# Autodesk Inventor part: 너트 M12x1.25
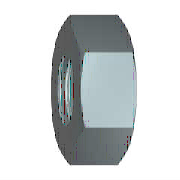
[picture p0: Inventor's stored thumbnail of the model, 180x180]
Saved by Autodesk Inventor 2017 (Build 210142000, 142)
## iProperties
IsCustomPart: 1
Created: 2012-02
Part Number: 너트 M12x1.25
Material: 강철, 연강
Description: 6각 너트
Document SubType Name: Modeling
Standard: KS B 1012
Designer: mduedu
Standards Organization: KS
Language: ko-KR
Size Designation: M12x1.25
Categories: <MemberInstance><Categories><Category DisplayName="조임쇠" InternalName="e4da775c-781d-43d5-af7c-5136215cf5a6" Mnemonic="FSTN"><Category DisplayName="너트" InternalN
Density: 1 g/cm^3
Appearance: Steel
Author: mduedu
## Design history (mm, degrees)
sketch "스케치1"
  geometry: L1 (-10.97, 0)-(-5.485, 9.5); L2 (-5.485, 9.5)-(5.485, 9.5); L3 (5.485, 9.5)-(10.97, 0); L4 (10.97, 0)-(5.485, -9.5); L5 (5.485, -9.5)-(-5.485, -9.5); L6 (-5.485, -9.5)-(-10.97, 0); 2 further points
  constraints: 12 end point, 1 coincident, 1 horizontal, 11 other
  dimensions: "d0" = 21.93931 distance of L3.end L1.start (= 1.1547 x SW)
extrude "본체" new body sketch "스케치1" distance "d1" = 10 (= KOH); taper "d2" = 0 deg
sketch "스케치2"
  geometry: L1 (0, 5.485)-(0, 10.97) reference; L2 (0, 10.97)-(10, 10.97) reference; L3 (10, 5.485)-(10, 10.97) reference; L4 (-2, 0)-(12, 0) reference; L5 (0.849, 10.97)-(0, 9.5); L6 (9.151, 10.97)-(10, 9.5)
  constraints: 4 end point, 4 point on line
  dimensions: "d3" = 30 deg angle of L1 L5 (= ANG1); "d4" = 30 deg angle of L3 L6 (= ANG2); "d5" = 19 diameter of L5.end L4 (= SW0); "d6" = 19 diameter of L6.end L4 (= SW01)
revolve "모따기1" sketch "스케치2" stored, may be unused: angle "d7" = 90 deg
sketch "스케치3"
  geometry: A1 r 9.5 centre (0, 0) between (-4.75, -8.227) and (4.75, -8.227) reference; 1 further point
  constraints: 1 coincident
hole "스레드" sketch "스케치3" at (0, 0) diameter "d25" = 10.647; stored, may be unused: countersink angle "d29" = 82 deg, drill point angle "d31" = 118 deg; dims "d26" = 6, "d27" = 4, "d28" = 2, "d30" = 8
workaxis "Work Axis1"
workplane "Work Plane1"
body "Solid1"
chamfer "모따기2" distance "d8" = 0.67658 (= -0.5 x GD1 + 0.5 x NND); stored, may be unused: angle "d9" = 30 deg, second distance "d40" = 0.67658 (= -0.5 x GD1 + 0.5 x NND)
chamfer "모따기3" distance "d10" = 0.67658 (= -0.5 x GD1 + 0.5 x NND); stored, may be unused: angle "d11" = 30 deg, second distance "d41" = 0.67658 (= -0.5 x GD1 + 0.5 x NND)
other parameters: "ANG1" = 30 deg [user parameter; used in 1 equation term], "ANG2" = 30 deg [user parameter; used in 1 equation term], "NND" = 12 [user parameter; used in 4 equation terms], "KOH" = 10 [user parameter; used in 1 equation term], "SW" = 19 [user parameter; used in 4 equation terms], "SW0" = 19 (= SW) [user parameter; used in 1 equation term], "SW01" = 19 (= SW) [user parameter; used in 1 equation term], "GD1" = 10.64684 (computed from THREADDIA, PTC, TOA) [user parameter; used in 4 equation terms], "d13" = 0, "d14" = 0, "d39" = 0, "d42" = 0, "GUL" = 0.67658 (= 0.541266 x PTC) [user parameter], "TPU" = 8 (computed from PTC) [user parameter], "THREADDIA" = 12 [user parameter; used in 1 equation term], "TOA" = 30 deg [user parameter; used in 1 equation term], "PTC" = 1.25 [user parameter; used in 4 equation terms], "E0" = 21.945 (= 1.155 x SW) [user parameter], "GAL" = 0.67658 (= 0.541266 x PTC) [user parameter]
